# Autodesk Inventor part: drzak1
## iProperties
Shininess: 64.0
Length Units: 11269
Angle Units: 11279
Time Units: 11290
Mass Units: 11283
Length Display Precision: 3
Angle Display Precision: 2
Compacted: True
Part Number: drzak1
Document SubType Name: Modeling
Created: 2008-05
Designer: Admin
Manufacturer: Standard
Standards Organization: Custom
Density: 0.0
Volumn: 0.0
Area: 0.0
PropertySet Name: Model Information
Control State: 0
Master: False
Checked Out: False
Author: Admin
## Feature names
1. Extrusion1
2. Extrusion2
3. Hole1
4. Extrusion3
